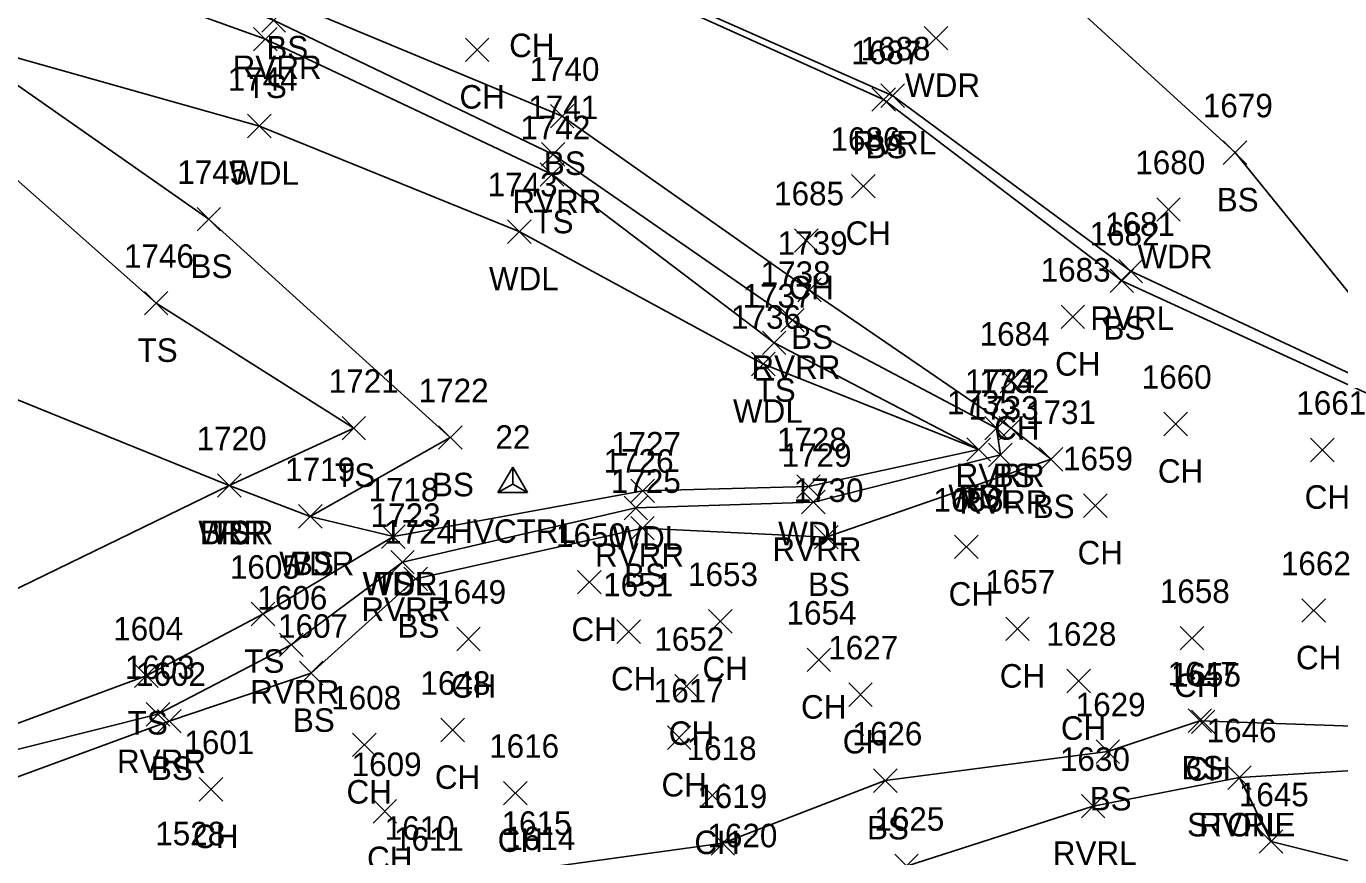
# Model space of a CAD drawing. Extents: x 1537342 to 1542195, y 163002 to 168596.
# Drawn here: x 1541827.1 to 1541938.8, y 163339 to 163409.7 of the extents above; entities that cross this region are included whole.
import ezdxf

# ---------------------------------------------------------------- set-up
doc = ezdxf.new("R2010")
doc.units = 0
for name, color, linetype in [('C_A', 7, 'Continuous'), ('C_I', 7, 'Continuous'), ('CPSM', 7, 'Continuous'), ('L_A', 7, 'Continuous'), ('L_I', 7, 'Continuous'), ('L_TIC', 7, 'Continuous'), ('LABL', 7, 'Continuous'), ('LASF', 7, 'Continuous'), ('LAWA', 7, 'Continuous'), ('LAWE', 7, 'Continuous'), ('LELB', 7, 'Continuous')]:
    doc.layers.add(name, color=color, linetype=linetype)

msp = doc.modelspace()

# ---------------------------------------------------------------- linework, layer by layer
at = {"layer": 'CPSM'}
for p, q in [((1541867.2, 163370), (1541868.45, 163372.16)), ((1541869.7, 163370), (1541868.45, 163372.16)), ((1541868.45, 163370.72), (1541868.45, 163372.16)), ((1541867.2, 163370), (1541868.45, 163370.72)), ((1541867.2, 163370), (1541869.7, 163370)), ((1541868.45, 163370.72), (1541868.45, 163370.72)), ((1541868.45, 163370.72), (1541869.7, 163370))]:
    msp.add_line(p, q, dxfattribs=at)
at = {"layer": 'L_TIC'}
for points in [[(1541847.11, 163409.16), (1541849.11, 163411.16)], [(1541849.11, 163409.16), (1541847.11, 163411.16)], [(1541846.41, 163407.55), (1541848.41, 163409.55)], [(1541848.41, 163407.55), (1541846.41, 163409.55)], [(1541903.46, 163407.64), (1541905.46, 163409.64)], [(1541905.46, 163407.64), (1541903.46, 163409.64)], [(1541864.43, 163406.65), (1541866.43, 163408.65)], [(1541866.43, 163406.65), (1541864.43, 163408.65)], [(1541899.78, 163402.75), (1541901.78, 163404.75)], [(1541901.78, 163402.75), (1541899.78, 163404.75)], [(1541899.01, 163402.43), (1541901.01, 163404.43)], [(1541901.01, 163402.43), (1541899.01, 163404.43)], [(1541871.66, 163401.01), (1541873.66, 163403.01)], [(1541873.66, 163401.01), (1541871.66, 163403.01)], [(1541845.9, 163400.17), (1541847.9, 163402.17)], [(1541847.9, 163400.17), (1541845.9, 163402.17)], [(1541870.9, 163397.76), (1541872.9, 163399.76)], [(1541872.9, 163397.76), (1541870.9, 163399.76)], [(1541928.91, 163397.91), (1541930.91, 163399.91)], [(1541930.91, 163397.91), (1541928.91, 163399.91)], [(1541870.8, 163396.05), (1541872.8, 163398.05)], [(1541872.8, 163396.05), (1541870.8, 163398.05)], [(1541897.28, 163395.06), (1541899.28, 163397.06)], [(1541899.28, 163395.06), (1541897.28, 163397.06)], [(1541923.25, 163393.07), (1541925.25, 163395.07)], [(1541925.25, 163393.07), (1541923.25, 163395.07)], [(1541841.6, 163392.25), (1541843.6, 163394.25)], [(1541843.6, 163392.25), (1541841.6, 163394.25)], [(1541868.01, 163391.19), (1541870.01, 163393.19)], [(1541870.01, 163391.19), (1541868.01, 163393.19)], [(1541892.43, 163390.43), (1541894.43, 163392.43)], [(1541894.43, 163390.43), (1541892.43, 163392.43)], [(1541919.27, 163387.01), (1541921.27, 163389.01)], [(1541921.27, 163387.01), (1541919.27, 163389.01)], [(1541920.03, 163387.83), (1541922.03, 163389.83)], [(1541922.03, 163387.83), (1541920.03, 163389.83)], [(1541892.7, 163386.22), (1541894.7, 163388.22)], [(1541894.7, 163386.22), (1541892.7, 163388.22)], [(1541837.12, 163385.11), (1541839.12, 163387.11)], [(1541839.12, 163385.11), (1541837.12, 163387.11)], [(1541891.25, 163383.66), (1541893.25, 163385.66)], [(1541893.25, 163383.66), (1541891.25, 163385.66)], [(1541915.11, 163383.94), (1541917.11, 163385.94)], [(1541917.11, 163383.94), (1541915.11, 163385.94)], [(1541889.7, 163381.73), (1541891.7, 163383.73)], [(1541891.7, 163381.73), (1541889.7, 163383.73)], [(1541888.78, 163379.93), (1541890.78, 163381.93)], [(1541890.78, 163379.93), (1541888.78, 163381.93)], [(1541909.92, 163378.49), (1541911.92, 163380.49)], [(1541911.92, 163378.49), (1541909.92, 163380.49)], [(1541923.85, 163374.83), (1541925.85, 163376.83)], [(1541925.85, 163374.83), (1541923.85, 163376.83)], [(1541853.93, 163374.48), (1541855.93, 163376.48)], [(1541855.93, 163374.48), (1541853.93, 163376.48)], [(1541862.14, 163373.68), (1541864.14, 163375.68)], [(1541864.14, 163373.68), (1541862.14, 163375.68)], [(1541908.62, 163374.47), (1541910.62, 163376.47)], [(1541910.62, 163374.47), (1541908.62, 163376.47)], [(1541909.85, 163374.47), (1541911.85, 163376.47)], [(1541911.85, 163374.47), (1541909.85, 163376.47)], [(1541907.1, 163372.66), (1541909.1, 163374.66)], [(1541909.1, 163372.66), (1541907.1, 163374.66)], [(1541907.1, 163372.66), (1541909.1, 163374.66)], [(1541909.1, 163372.66), (1541907.1, 163374.66)], [(1541936.34, 163372.62), (1541938.34, 163374.62)], [(1541938.34, 163372.62), (1541936.34, 163374.62)], [(1541908.94, 163372.2), (1541910.94, 163374.2)], [(1541910.94, 163372.2), (1541908.94, 163374.2)], [(1541913.25, 163371.83), (1541915.25, 163373.83)], [(1541915.25, 163371.83), (1541913.25, 163373.83)], [(1541843.34, 163369.6), (1541845.34, 163371.6)], [(1541845.34, 163369.6), (1541843.34, 163371.6)], [(1541843.34, 163369.6), (1541845.34, 163371.6)], [(1541845.34, 163369.6), (1541843.34, 163371.6)], [(1541843.34, 163369.6), (1541845.34, 163371.6)], [(1541845.34, 163369.6), (1541843.34, 163371.6)], [(1541878.51, 163369.15), (1541880.51, 163371.15)], [(1541880.51, 163369.15), (1541878.51, 163371.15)], [(1541892.62, 163369.51), (1541894.62, 163371.51)], [(1541894.62, 163369.51), (1541892.62, 163371.51)], [(1541893.03, 163368.19), (1541895.03, 163370.19)], [(1541895.03, 163368.19), (1541893.03, 163370.19)], [(1541850.23, 163366.97), (1541852.23, 163368.97)], [(1541852.23, 163366.97), (1541850.23, 163368.97)], [(1541850.23, 163366.97), (1541852.23, 163368.97)], [(1541852.23, 163366.97), (1541850.23, 163368.97)], [(1541877.93, 163367.69), (1541879.93, 163369.69)], [(1541879.93, 163367.69), (1541877.93, 163369.69)], [(1541917.02, 163367.89), (1541919.02, 163369.89)], [(1541919.02, 163367.89), (1541917.02, 163369.89)], [(1541878.49, 163365.97), (1541880.49, 163367.97)], [(1541880.49, 163365.97), (1541878.49, 163367.97)], [(1541857.3, 163365.25), (1541859.3, 163367.25)], [(1541859.3, 163365.25), (1541857.3, 163367.25)], [(1541857.3, 163365.25), (1541859.3, 163367.25)], [(1541859.3, 163365.25), (1541857.3, 163367.25)], [(1541857.3, 163365.25), (1541859.3, 163367.25)], [(1541859.3, 163365.25), (1541857.3, 163367.25)], [(1541894.13, 163365.2), (1541896.13, 163367.2)], [(1541896.13, 163365.2), (1541894.13, 163367.2)], [(1541906.05, 163364.38), (1541908.05, 163366.38)], [(1541908.05, 163364.38), (1541906.05, 163366.38)], [(1541858.07, 163363.08), (1541860.07, 163365.08)], [(1541860.07, 163363.08), (1541858.07, 163365.08)], [(1541859.2, 163361.66), (1541861.2, 163363.66)], [(1541861.2, 163361.66), (1541859.2, 163363.66)], [(1541873.97, 163361.38), (1541875.97, 163363.38)], [(1541875.97, 163361.38), (1541873.97, 163363.38)], [(1541846.2, 163358.67), (1541848.2, 163360.67)], [(1541848.2, 163358.67), (1541846.2, 163360.67)], [(1541885.11, 163358.05), (1541887.11, 163360.05)], [(1541887.11, 163358.05), (1541885.11, 163360.05)], [(1541935.6, 163358.97), (1541937.6, 163360.97)], [(1541937.6, 163358.97), (1541935.6, 163360.97)], [(1541877.32, 163357.17), (1541879.32, 163359.17)], [(1541879.32, 163357.17), (1541877.32, 163359.17)], [(1541910.4, 163357.41), (1541912.4, 163359.41)], [(1541912.4, 163357.41), (1541910.4, 163359.41)], [(1541848.61, 163356.05), (1541850.61, 163358.05)], [(1541850.61, 163356.05), (1541848.61, 163358.05)], [(1541863.69, 163356.55), (1541865.69, 163358.55)], [(1541865.69, 163356.55), (1541863.69, 163358.55)], [(1541925.25, 163356.61), (1541927.25, 163358.61)], [(1541927.25, 163356.61), (1541925.25, 163358.61)], [(1541893.49, 163354.77), (1541895.49, 163356.77)], [(1541895.49, 163354.77), (1541893.49, 163356.77)], [(1541850.31, 163353.65), (1541852.31, 163355.65)], [(1541852.31, 163353.65), (1541850.31, 163355.65)], [(1541836.28, 163353.42), (1541838.28, 163355.42)], [(1541838.28, 163353.42), (1541836.28, 163355.42)], [(1541882.24, 163352.54), (1541884.24, 163354.54)], [(1541884.24, 163352.54), (1541882.24, 163354.54)], [(1541915.6, 163352.97), (1541917.6, 163354.97)], [(1541917.6, 163352.97), (1541915.6, 163354.97)], [(1541897.04, 163351.81), (1541899.04, 163353.81)], [(1541899.04, 163351.81), (1541897.04, 163353.81)], [(1541837.27, 163350.14), (1541839.27, 163352.14)], [(1541839.27, 163350.14), (1541837.27, 163352.14)], [(1541838.23, 163349.56), (1541840.23, 163351.56)], [(1541840.23, 163349.56), (1541838.23, 163351.56)], [(1541925.91, 163349.6), (1541927.91, 163351.6)], [(1541927.91, 163349.6), (1541925.91, 163351.6)], [(1541926.2, 163349.5), (1541928.2, 163351.5)], [(1541928.2, 163349.5), (1541926.2, 163351.5)], [(1541862.34, 163348.8), (1541864.34, 163350.8)], [(1541864.34, 163348.8), (1541862.34, 163350.8)], [(1541881.62, 163348.15), (1541883.62, 163350.15)], [(1541883.62, 163348.15), (1541881.62, 163350.15)], [(1541854.83, 163347.55), (1541856.83, 163349.55)], [(1541856.83, 163347.55), (1541854.83, 163349.55)], [(1541918.09, 163346.97), (1541920.09, 163348.97)], [(1541920.09, 163346.97), (1541918.09, 163348.97)], [(1541929.29, 163344.76), (1541931.29, 163346.76)], [(1541931.29, 163344.76), (1541929.29, 163346.76)], [(1541929.29, 163344.76), (1541931.29, 163346.76)], [(1541931.29, 163344.76), (1541929.29, 163346.76)], [(1541841.78, 163343.76), (1541843.78, 163345.76)], [(1541843.78, 163343.76), (1541841.78, 163345.76)], [(1541867.68, 163343.44), (1541869.68, 163345.44)], [(1541869.68, 163343.44), (1541867.68, 163345.44)], [(1541899.15, 163344.5), (1541901.15, 163346.5)], [(1541901.15, 163344.5), (1541899.15, 163346.5)], [(1541884.43, 163343.25), (1541886.43, 163345.25)], [(1541886.43, 163343.25), (1541884.43, 163345.25)], [(1541916.84, 163342.33), (1541918.84, 163344.33)], [(1541918.84, 163342.33), (1541916.84, 163344.33)], [(1541856.57, 163341.89), (1541858.57, 163343.89)], [(1541858.57, 163341.89), (1541856.57, 163343.89)], [(1541885.33, 163339.17), (1541887.33, 163341.17)], [(1541887.33, 163339.17), (1541885.33, 163341.17)], [(1541931.97, 163339.32), (1541933.97, 163341.32)], [(1541933.97, 163339.32), (1541931.97, 163341.32)], [(1541900.96, 163337.24), (1541902.96, 163339.24)], [(1541902.96, 163337.24), (1541900.96, 163339.24)]]:
    msp.add_lwpolyline(points, dxfattribs=at)
at = {"layer": 'LABL'}
msp.add_lwpolyline([(1541844.34, 163370.6), (1541821.33, 163359.44), (1541813.12, 163355.49), (1541797.38, 163365.13), (1541723.78, 163418.04)], dxfattribs=at)
at = {"layer": 'LASF'}
msp.add_lwpolyline([(1541995.88, 163321.62), (1541975.61, 163331.57), (1541964.35, 163336.56), (1541946.91, 163336.83), (1541932.97, 163340.32), (1541930.29, 163345.76)], dxfattribs=at)
at = {"layer": 'LAWA'}
for points in [[(1541858.3, 163366.25), (1541851.23, 163367.97), (1541844.34, 163370.6), (1541815.36, 163382.31), (1541797.41, 163395.47), (1541778.64, 163400.7), (1541758.29, 163411.82), (1541723.78, 163418.04), (1541697.04, 163431.45), (1541651.96, 163468.67), (1541626.15, 163491.84), (1541623.99, 163498.52), (1541617.66, 163502.86), (1541594.18, 163514.44)], [(1541858.3, 163366.25), (1541879.51, 163370.15), (1541893.62, 163370.51), (1541908.1, 163373.66), (1541889.78, 163380.93), (1541869.01, 163392.19), (1541846.9, 163401.17), (1541820.74, 163408.53), (1541800.16, 163418.36), (1541771.31, 163422.69), (1541733.43, 163438.83), (1541707.98, 163450.9), (1541667.55, 163486.78), (1541634.88, 163501.17)]]:
    msp.add_lwpolyline(points, dxfattribs=at)
at = {"layer": 'LAWE'}
for points in [[(1541807.79, 163344.41), (1541817.37, 163345.92), (1541838.27, 163351.14), (1541849.61, 163357.05), (1541859.07, 163364.08), (1541878.93, 163368.69), (1541894.03, 163369.19), (1541909.94, 163373.2), (1541909.62, 163375.47), (1541892.25, 163384.66), (1541871.9, 163398.76), (1541848.11, 163410.16), (1541823.72, 163419.67), (1541801.87, 163424.04), (1541777.04, 163426.76), (1541733.23, 163439.48), (1541709.17, 163452.19), (1541667.42, 163488.13), (1541636.18, 163502.23)], [(1541964.97, 163374.84), (1541943.31, 163378.43), (1541921.03, 163388.83), (1541900.78, 163403.75), (1541870.95, 163416.96), (1541842.26, 163431.79), (1541812.16, 163446.74), (1541779.01, 163455.02), (1541742.66, 163469.64)], [(1541842.54, 163329.29), (1541847.22, 163332.13), (1541859.96, 163336.54), (1541870, 163336.59), (1541887.85, 163336.83), (1541901.96, 163338.24), (1541917.84, 163343.33), (1541930.29, 163345.76), (1541946.35, 163346.77), (1541962.46, 163344.96)]]:
    msp.add_lwpolyline(points, dxfattribs=at)
at = {"layer": 'LELB'}
for points in [[(1541964.73, 163370.11), (1541945.07, 163376.64), (1541920.27, 163388.01), (1541900.01, 163403.43), (1541870.81, 163416.57), (1541842.39, 163430.68), (1541811.88, 163446.01), (1541778.73, 163450.23), (1541740.6, 163464.39)], [(1541943.1, 163382.66), (1541929.91, 163398.91), (1541907.78, 163419.17), (1541886.16, 163442.24)], [(1541908.1, 163373.66), (1541890.7, 163382.73), (1541871.8, 163397.05), (1541847.41, 163408.55), (1541821.84, 163417.77), (1541801.87, 163424.04)], [(1541844.34, 163370.6), (1541854.93, 163375.48), (1541838.12, 163386.11), (1541819.72, 163402.38), (1541799.78, 163411.2), (1541771.31, 163422.69)], [(1541680.48, 163291.86), (1541699.97, 163293.9), (1541717.14, 163294.13), (1541730.52, 163297.57), (1541741.65, 163302.35), (1541748.18, 163305.38), (1541748.08, 163309.08), (1541755.23, 163315.37), (1541766.51, 163324.36), (1541774.32, 163324.47), (1541783.87, 163329.52), (1541794.38, 163332.12), (1541806.54, 163337.4), (1541818.82, 163343.08), (1541839.23, 163350.56), (1541851.31, 163354.65), (1541860.2, 163362.66), (1541879.49, 163366.97), (1541895.13, 163366.2), (1541914.25, 163372.83), (1541910.85, 163375.47), (1541893.7, 163387.22), (1541872.66, 163402.01), (1541849.05, 163411.83)], [(1541851.23, 163367.97), (1541863.14, 163374.68), (1541842.6, 163393.25), (1541820.74, 163408.53)], [(1541807.79, 163344.41), (1541817.08, 163346.96), (1541837.28, 163354.42), (1541847.2, 163359.67), (1541858.3, 163366.25)], [(1541832.78, 163328.58), (1541834.66, 163331.5), (1541843.37, 163333.29), (1541847.54, 163333.68), (1541859.82, 163337.47), (1541869.67, 163337.89), (1541886.33, 163340.17), (1541900.15, 163345.5), (1541919.09, 163347.97), (1541926.91, 163350.6), (1541947.26, 163349.87), (1541963.47, 163346.82)]]:
    msp.add_lwpolyline(points, dxfattribs=at)

# ---------------------------------------------------------------- texts
at = {"layer": 'C_A'}
msp.add_text('HVCTRL', height=2, dxfattribs=at).set_placement((1541863.14, 163365.72))
at = {"layer": 'C_I'}
msp.add_text('22', height=2, dxfattribs=at).set_placement((1541866.98, 163373.72))
at = {"layer": 'L_A'}
for s, p in [('BS', (1541847.49, 163406.83)), ('CH', (1541868.15, 163407.03)), ('RVRR', (1541844.62, 163405.16)), ('TS', (1541845.82, 163403.55)), ('CH', (1541863.92, 163402.65)), ('WDR', (1541901.83, 163403.64)), ('RVRL', (1541897.35, 163398.75)), ('BS', (1541898.45, 163398.43)), ('WDL', (1541844.32, 163396.17)), ('BS', (1541871.1, 163397.01)), ('RVRR', (1541868.42, 163393.76)), ('BS', (1541928.35, 163393.91)), ('TS', (1541870.21, 163392.05)), ('CH', (1541896.77, 163391.06)), ('BS', (1541841.04, 163388.25)), ('WDR', (1541921.61, 163389.07)), ('WDL', (1541866.43, 163387.19)), ('CH', (1541891.92, 163386.43)), ('RVRL', (1541917.59, 163383.83)), ('BS', (1541918.71, 163383.01)), ('BS', (1541892.14, 163382.22)), ('TS', (1541836.53, 163381.11)), ('RVRR', (1541888.76, 163379.66)), ('CH', (1541914.6, 163379.94)), ('TS', (1541889.11, 163377.73)), ('WDL', (1541887.19, 163375.93)), ('CH', (1541909.41, 163374.49)), ('TS', (1541853.34, 163370.48)), ('RVRR', (1541906.13, 163370.47)), ('BS', (1541909.29, 163370.47)), ('CH', (1541923.34, 163370.83)), ('BS', (1541861.58, 163369.68)), ('WDL', (1541905.52, 163368.66)), ('TS', (1541906.51, 163368.66)), ('RVRR', (1541906.45, 163368.2)), ('CH', (1541935.83, 163368.62)), ('BS', (1541912.69, 163367.83)), ('WDR', (1541841.71, 163365.6)), ('BRR', (1541841.83, 163365.6)), ('TS', (1541842.75, 163365.6)), ('WDL', (1541876.93, 163365.15)), ('WDL', (1541891.04, 163365.51)), ('RVRR', (1541875.45, 163363.69)), ('RVRR', (1541890.54, 163364.19)), ('CH', (1541916.51, 163363.89)), ('WDR', (1541848.59, 163362.97)), ('BS', (1541849.67, 163362.97)), ('TS', (1541856.71, 163361.25)), ('BS', (1541877.93, 163361.97)), ('WDR', (1541855.67, 163361.25)), ('WDL', (1541855.72, 163361.25)), ('BS', (1541893.57, 163361.2)), ('CH', (1541905.54, 163360.38)), ('RVRR', (1541855.58, 163359.08)), ('BS', (1541858.65, 163357.66)), ('CH', (1541873.45, 163357.38)), ('TS', (1541845.61, 163354.67)), ('CH', (1541935.09, 163354.97)), ('CH', (1541884.6, 163354.05)), ('CH', (1541863.18, 163352.55)), ('CH', (1541876.81, 163353.17)), ('CH', (1541909.89, 163353.41)), ('CH', (1541924.73, 163352.61)), ('RVRR', (1541846.12, 163352.05)), ('CH', (1541892.98, 163350.77)), ('TS', (1541835.69, 163349.42)), ('BS', (1541849.75, 163349.65)), ('CH', (1541915.09, 163348.97)), ('CH', (1541881.73, 163348.54)), ('CH', (1541896.53, 163347.81)), ('RVRR', (1541834.78, 163346.14)), ('BS', (1541837.67, 163345.56)), ('CH', (1541861.83, 163344.8)), ('BS', (1541925.35, 163345.6)), ('CH', (1541925.69, 163345.5)), ('CH', (1541854.31, 163343.55)), ('CH', (1541881.11, 163344.15)), ('BS', (1541917.54, 163342.97)), ('BS', (1541898.59, 163340.5)), ('STONE', (1541925.83, 163340.76)), ('RVRL', (1541926.85, 163340.76)), ('CH', (1541841.26, 163339.76)), ('CH', (1541867.17, 163339.44)), ('CH', (1541883.91, 163339.25)), ('CH', (1541856.06, 163337.89)), ('RVRL', (1541914.4, 163338.33))]:
    msp.add_text(s, height=2, dxfattribs=at).set_placement(p)
at = {"layer": 'L_I'}
for s, p in [('1687', (1541897.27, 163406.43)), ('1688', (1541898.04, 163406.75)), ('1740', (1541869.88, 163405.01)), ('1744', (1541844.21, 163404.17)), ('1741', (1541869.78, 163401.76)), ('1679', (1541927.17, 163401.91)), ('1742', (1541869.11, 163400.05)), ('1686', (1541895.49, 163399.06)), ('1680', (1541921.42, 163397.07)), ('1745', (1541839.91, 163396.25)), ('1743', (1541866.32, 163395.19)), ('1685', (1541890.69, 163394.43)), ('1681', (1541918.85, 163391.83)), ('1682', (1541917.53, 163391.01)), ('1739', (1541891, 163390.22)), ('1746', (1541835.38, 163389.11)), ('1738', (1541889.55, 163387.66)), ('1683', (1541913.37, 163387.94)), ('1737', (1541888.01, 163385.73)), ('1736', (1541887.03, 163383.93)), ('1684', (1541908.18, 163382.49)), ('1721', (1541852.8, 163378.48)), ('1734', (1541906.93, 163378.47)), ('1732', (1541908.15, 163378.47)), ('1660', (1541921.97, 163378.83)), ('1722', (1541860.45, 163377.68)), ('1735', (1541905.41, 163376.66)), ('1735', (1541905.41, 163376.66)), ('1733', (1541907.25, 163376.2)), ('1731', (1541912.13, 163375.83)), ('1661', (1541935.12, 163376.62)), ('1720', (1541841.56, 163373.6)), ('1720', (1541841.56, 163373.6)), ('1720', (1541841.56, 163373.6)), ('1727', (1541876.82, 163373.15)), ('1728', (1541890.93, 163373.51)), ('1726', (1541876.19, 163371.69)), ('1729', (1541891.33, 163372.19)), ('1659', (1541915.27, 163371.89)), ('1719', (1541849.09, 163370.97)), ('1719', (1541849.09, 163370.97)), ('1718', (1541856.18, 163369.25)), ('1718', (1541856.18, 163369.25)), ('1718', (1541856.18, 163369.25)), ('1725', (1541876.8, 163369.97)), ('1730', (1541892.35, 163369.2)), ('1656', (1541904.25, 163368.38)), ('1723', (1541856.37, 163367.08)), ('1724', (1541857.51, 163365.66)), ('1650', (1541872.14, 163365.38)), ('1605', (1541844.39, 163362.67)), ('1662', (1541933.81, 163362.97)), ('1653', (1541883.37, 163362.05)), ('1657', (1541908.66, 163361.41)), ('1649', (1541861.94, 163360.55)), ('1651', (1541876.15, 163361.17)), ('1658', (1541923.51, 163360.61)), ('1606', (1541846.73, 163360.05)), ('1654', (1541891.75, 163358.77)), ('1604', (1541834.46, 163357.42)), ('1607', (1541848.49, 163357.65)), ('1628', (1541913.86, 163356.97)), ('1652', (1541880.5, 163356.54)), ('1627', (1541895.3, 163355.81)), ('1603', (1541835.45, 163354.14)), ('1602', (1541836.41, 163353.56)), ('1647', (1541924.17, 163353.6)), ('1655', (1541924.46, 163353.5)), ('1648', (1541860.6, 163352.8)), ('1608', (1541853.01, 163351.55)), ('1617', (1541880.45, 163352.15)), ('1629', (1541916.35, 163350.97)), ('1626', (1541897.35, 163348.5)), ('1646', (1541927.49, 163348.76)), ('1646', (1541927.49, 163348.76)), ('1601', (1541840.52, 163347.76)), ('1616', (1541866.45, 163347.44)), ('1618', (1541883.25, 163347.25)), ('1609', (1541854.75, 163345.89)), ('1630', (1541915.01, 163346.33)), ('1619', (1541884.15, 163343.17)), ('1645', (1541930.23, 163343.32)), ('1625', (1541899.22, 163341.24)), ('1610', (1541857.56, 163340.47)), ('1615', (1541867.5, 163340.89)), ('1528', (1541838.04, 163340)), ('1611', (1541858.35, 163339.54)), ('1614', (1541867.83, 163339.59)), ('1620', (1541885.02, 163339.83))]:
    msp.add_text(s, height=2, dxfattribs=at).set_placement(p)

doc.saveas('drawing.dxf')
